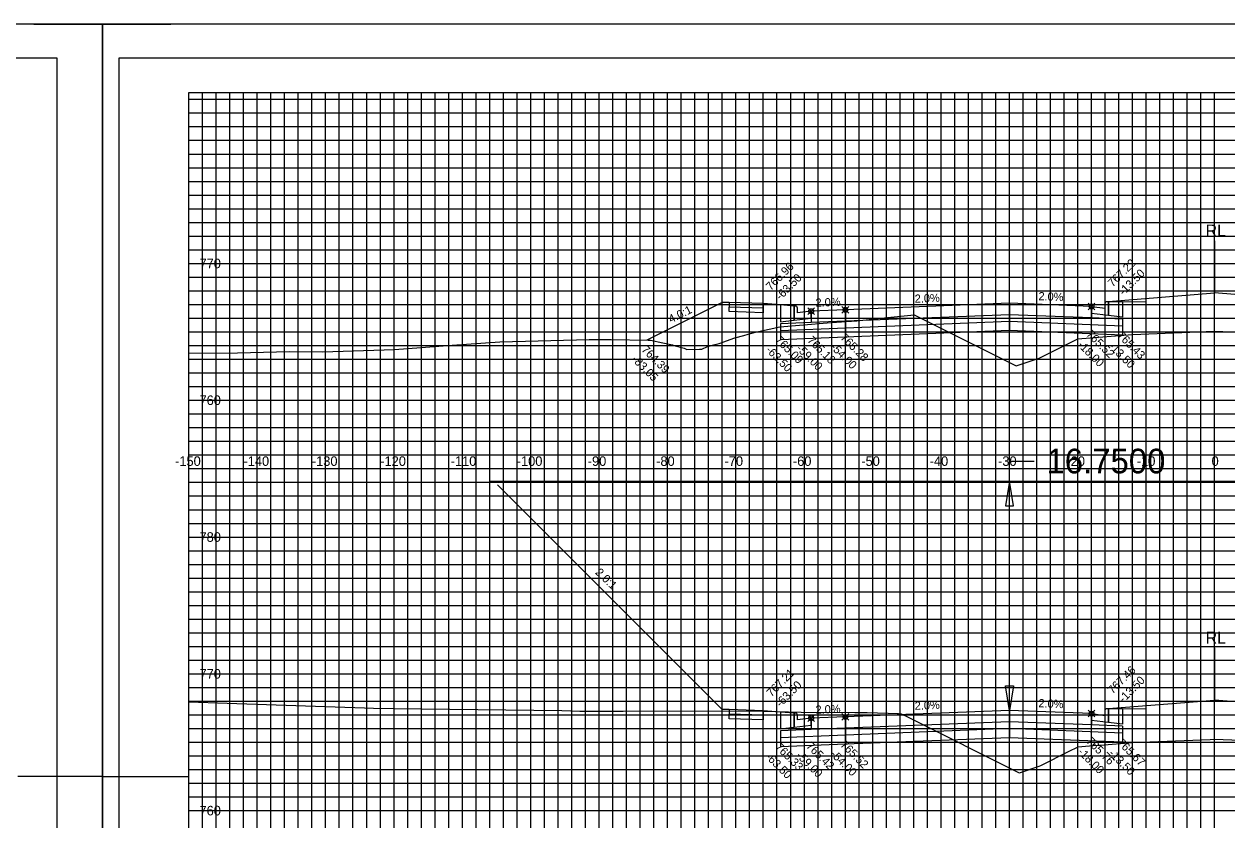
# Model space of a CAD drawing. Extents: x 578243 to 601557, y 174899 to 175559.
# Drawn here: x 600865.7 to 601041.6, y 175002.4 to 175118.8 of the extents above; entities that cross this region are included whole.
import ezdxf

# ---------------------------------------------------------------- set-up
doc = ezdxf.new("R2010")
doc.units = 0
for name, color, linetype in [('E_PROF_Grid', 7, 'Continuous'), ('E_PROF_GridMin', 7, 'Continuous'), ('P_CRDR_Label', 7, 'Continuous'), ('P_CRDR_Link', 7, 'Continuous'), ('P_E_XS_Ground', 7, 'Continuous'), ('P_RW_SlopeIntercepts', 7, 'Continuous'), ('P_XS_Text', 7, 'Continuous'), ('PLT_Sheet_Border', 7, 'Continuous'), ('PLT_Sheet_Info', 7, 'Continuous')]:
    doc.layers.add(name, color=color, linetype=linetype)

msp = doc.modelspace()

# ---------------------------------------------------------------- linework, layer by layer
at = {"layer": 'E_PROF_Grid'}
for p, q in [((600899.84, 174913.8), (600899.84, 175108.8)), ((600909.84, 174913.8), (600909.84, 175108.8)), ((600919.84, 174913.8), (600919.84, 175108.8)), ((600929.84, 174913.8), (600929.84, 175108.8)), ((600939.84, 174913.8), (600939.84, 175108.8)), ((600949.84, 174913.8), (600949.84, 175108.8)), ((600959.84, 174913.8), (600959.84, 175108.8)), ((600969.84, 174913.8), (600969.84, 175108.8)), ((600979.84, 174913.8), (600979.84, 175108.8)), ((600989.84, 174913.8), (600989.84, 175108.8)), ((600999.84, 174913.8), (600999.84, 175108.8)), ((601009.84, 174913.8), (601009.84, 175108.8)), ((601019.84, 174913.8), (601019.84, 175108.8)), ((601029.84, 174913.8), (601029.84, 175108.8)), ((601039.84, 174913.8), (601039.84, 175108.8)), ((600889.84, 175103.8), (601204.84, 175103.8)), ((600889.84, 175093.8), (601204.84, 175093.8)), ((600889.84, 175083.8), (601204.84, 175083.8)), ((600889.84, 175073.8), (601204.84, 175073.8)), ((600889.84, 175063.8), (601204.84, 175063.8)), ((600889.84, 175053.8), (601204.84, 175053.8)), ((600889.84, 175043.8), (601204.84, 175043.8)), ((600889.84, 175033.8), (601204.84, 175033.8)), ((600889.84, 175023.8), (601204.84, 175023.8)), ((600889.84, 175013.8), (601204.84, 175013.8)), ((600889.84, 175003.8), (601204.84, 175003.8))]:
    msp.add_line(p, q, dxfattribs=at)
at = {"layer": 'E_PROF_GridMin'}
for p, q in [((600891.84, 174913.8), (600891.84, 175108.8)), ((600893.84, 174913.8), (600893.84, 175108.8)), ((600895.84, 174913.8), (600895.84, 175108.8)), ((600897.84, 174913.8), (600897.84, 175108.8)), ((600901.84, 174913.8), (600901.84, 175108.8)), ((600903.84, 174913.8), (600903.84, 175108.8)), ((600905.84, 174913.8), (600905.84, 175108.8)), ((600907.84, 174913.8), (600907.84, 175108.8)), ((600911.84, 174913.8), (600911.84, 175108.8)), ((600913.84, 174913.8), (600913.84, 175108.8)), ((600915.84, 174913.8), (600915.84, 175108.8)), ((600917.84, 174913.8), (600917.84, 175108.8)), ((600921.84, 174913.8), (600921.84, 175108.8)), ((600923.84, 174913.8), (600923.84, 175108.8)), ((600925.84, 174913.8), (600925.84, 175108.8)), ((600927.84, 174913.8), (600927.84, 175108.8)), ((600931.84, 174913.8), (600931.84, 175108.8)), ((600933.84, 174913.8), (600933.84, 175108.8)), ((600935.84, 174913.8), (600935.84, 175108.8)), ((600937.84, 174913.8), (600937.84, 175108.8)), ((600941.84, 174913.8), (600941.84, 175108.8)), ((600943.84, 174913.8), (600943.84, 175108.8)), ((600945.84, 174913.8), (600945.84, 175108.8)), ((600947.84, 174913.8), (600947.84, 175108.8)), ((600951.84, 174913.8), (600951.84, 175108.8)), ((600953.84, 174913.8), (600953.84, 175108.8)), ((600955.84, 174913.8), (600955.84, 175108.8)), ((600957.84, 174913.8), (600957.84, 175108.8)), ((600961.84, 174913.8), (600961.84, 175108.8)), ((600963.84, 174913.8), (600963.84, 175108.8)), ((600965.84, 174913.8), (600965.84, 175108.8)), ((600967.84, 174913.8), (600967.84, 175108.8)), ((600971.84, 174913.8), (600971.84, 175108.8)), ((600973.84, 174913.8), (600973.84, 175108.8)), ((600975.84, 174913.8), (600975.84, 175108.8)), ((600977.84, 174913.8), (600977.84, 175108.8)), ((600981.84, 174913.8), (600981.84, 175108.8)), ((600983.84, 174913.8), (600983.84, 175108.8)), ((600985.84, 174913.8), (600985.84, 175108.8)), ((600987.84, 174913.8), (600987.84, 175108.8)), ((600991.84, 174913.8), (600991.84, 175108.8)), ((600993.84, 174913.8), (600993.84, 175108.8)), ((600995.84, 174913.8), (600995.84, 175108.8)), ((600997.84, 174913.8), (600997.84, 175108.8)), ((601001.84, 174913.8), (601001.84, 175108.8)), ((601003.84, 174913.8), (601003.84, 175108.8)), ((601005.84, 174913.8), (601005.84, 175108.8)), ((601007.84, 174913.8), (601007.84, 175108.8)), ((601011.84, 174913.8), (601011.84, 175108.8)), ((601013.84, 174913.8), (601013.84, 175108.8)), ((601015.84, 174913.8), (601015.84, 175108.8)), ((601017.84, 174913.8), (601017.84, 175108.8)), ((601021.84, 174913.8), (601021.84, 175108.8)), ((601023.84, 174913.8), (601023.84, 175108.8)), ((601025.84, 174913.8), (601025.84, 175108.8)), ((601027.84, 174913.8), (601027.84, 175108.8)), ((601031.84, 174913.8), (601031.84, 175108.8)), ((601033.84, 174913.8), (601033.84, 175108.8)), ((601035.84, 174913.8), (601035.84, 175108.8)), ((601037.84, 174913.8), (601037.84, 175108.8)), ((600889.84, 175107.8), (601204.84, 175107.8)), ((600889.84, 175105.8), (601204.84, 175105.8)), ((600889.84, 175101.8), (601204.84, 175101.8)), ((600889.84, 175099.8), (601204.84, 175099.8)), ((600889.84, 175097.8), (601204.84, 175097.8)), ((600889.84, 175095.8), (601204.84, 175095.8)), ((600889.84, 175091.8), (601204.84, 175091.8)), ((600889.84, 175089.8), (601204.84, 175089.8)), ((600889.84, 175087.8), (601204.84, 175087.8)), ((600889.84, 175085.8), (601204.84, 175085.8)), ((600889.84, 175081.8), (601204.84, 175081.8)), ((600889.84, 175079.8), (601204.84, 175079.8)), ((600889.84, 175077.8), (601204.84, 175077.8)), ((600889.84, 175075.8), (601204.84, 175075.8)), ((600889.84, 175071.8), (601204.84, 175071.8)), ((600889.84, 175069.8), (601204.84, 175069.8)), ((600889.84, 175067.8), (601204.84, 175067.8)), ((600889.84, 175065.8), (601204.84, 175065.8)), ((600889.84, 175061.8), (601204.84, 175061.8)), ((600889.84, 175059.8), (601204.84, 175059.8)), ((600889.84, 175057.8), (601204.84, 175057.8)), ((600889.84, 175055.8), (601204.84, 175055.8)), ((600889.84, 175051.8), (601204.84, 175051.8)), ((600889.84, 175049.8), (601204.84, 175049.8)), ((600889.84, 175047.8), (601204.84, 175047.8)), ((600889.84, 175045.8), (601204.84, 175045.8)), ((600889.84, 175041.8), (601204.84, 175041.8)), ((600889.84, 175039.8), (601204.84, 175039.8)), ((600889.84, 175037.8), (601204.84, 175037.8)), ((600889.84, 175035.8), (601204.84, 175035.8)), ((600889.84, 175031.8), (601204.84, 175031.8)), ((600889.84, 175029.8), (601204.84, 175029.8)), ((600889.84, 175027.8), (601204.84, 175027.8)), ((600889.84, 175025.8), (601204.84, 175025.8)), ((600889.84, 175021.8), (601204.84, 175021.8)), ((600889.84, 175019.8), (601204.84, 175019.8)), ((600889.84, 175017.8), (601204.84, 175017.8)), ((600889.84, 175015.8), (601204.84, 175015.8)), ((600889.84, 175011.8), (601204.84, 175011.8)), ((600889.84, 175009.8), (601204.84, 175009.8)), ((600889.84, 175007.8), (601204.84, 175007.8)), ((600889.84, 175005.8), (601204.84, 175005.8))]:
    msp.add_line(p, q, dxfattribs=at)
at = {"layer": 'P_CRDR_Label'}
for points in [[(601039.84, 175087.11), (601039.84, 175079.49)], [(600980.34, 175076.32), (600981.33, 175077.31)], [(600980.34, 175077.31), (600981.33, 175076.32)], [(600985.34, 175076.52), (600986.33, 175077.51)], [(600985.34, 175077.51), (600986.33, 175076.52)], [(601021.34, 175077), (601022.33, 175077.99)], [(601021.34, 175077.99), (601022.33, 175077)], [(601039.84, 175027.6), (601039.84, 175019.97)], [(600980.34, 175016.81), (600981.33, 175017.8)], [(600980.34, 175017.8), (600981.33, 175016.81)], [(600985.34, 175017.01), (600986.33, 175018)], [(600985.34, 175018), (600986.33, 175017.01)], [(601021.34, 175017.49), (601022.33, 175018.48)], [(601021.34, 175018.48), (601022.33, 175017.49)]]:
    msp.add_lwpolyline(points, dxfattribs=at)
for centre in [(600980.84, 175076.82), (600985.84, 175077.02), (601021.84, 175077.5), (600980.84, 175017.3), (600985.84, 175017.5), (601021.84, 175017.98)]:
    msp.add_circle(centre, 0.35, dxfattribs=at)
at = {"layer": 'P_CRDR_Link'}
msp.add_line((600934.99, 175051.44), (600967.84, 175018.59), dxfattribs=at)
for points in [[(601024.34, 175078.25), (601039.84, 175079.49)], [(601024.34, 175078.25), (601039.84, 175079.49)], [(601055.34, 175078.25), (601039.84, 175079.49)], [(601055.34, 175078.25), (601039.84, 175079.49)], [(600967.84, 175078.11), (600956.79, 175072.58)], [(600967.84, 175078.11), (600956.79, 175072.58)], [(600968.84, 175078.08), (600967.84, 175078.11)], [(600968.84, 175078.08), (600967.84, 175078.11)], [(600973.84, 175077.93), (600968.84, 175078.08)], [(600973.84, 175077.93), (600968.84, 175078.08)], [(600968.84, 175078.08), (600968.84, 175077.41)], [(600973.83, 175077.26), (600968.84, 175077.41)], [(600968.85, 175076.75), (600968.84, 175077.41)], [(600973.84, 175077.93), (600973.83, 175077.26)], [(600973.83, 175077.26), (600973.83, 175076.6)], [(600976.34, 175077.73), (600973.84, 175077.93)], [(600976.34, 175077.73), (600973.84, 175077.93)], [(600978.34, 175077.57), (600976.34, 175077.73)], [(600976.34, 175077.73), (600976.34, 175075.25)], [(600976.34, 175077.73), (600976.34, 175075.25)], [(600976.34, 175077.73), (600976.34, 175075.25)], [(600978.66, 175077.57), (600978.34, 175077.57)], [(600978.66, 175077.57), (600978.34, 175077.57)], [(600978.34, 175077.57), (600978.34, 175075.5)], [(600978.34, 175075.5), (600978.34, 175077.57)], [(600978.74, 175077.52), (600978.66, 175077.57)], [(600978.74, 175077.52), (600978.66, 175077.57)], [(600978.8, 175077.41), (600978.74, 175077.52)], [(600978.8, 175077.41), (600978.74, 175077.52)], [(600978.83, 175077.25), (600978.8, 175077.41)], [(600978.83, 175077.25), (600978.8, 175077.41)], [(600978.84, 175076.57), (600978.83, 175077.25)], [(600978.84, 175076.57), (600978.83, 175077.25)], [(600985.84, 175077.02), (600980.84, 175076.82)], [(601009.84, 175077.98), (600985.84, 175077.02)], [(600985.84, 175077.02), (600985.84, 175075.35)], [(600985.84, 175077.02), (600985.84, 175075.35)], [(601021.84, 175077.5), (601009.84, 175077.98)], [(601009.84, 175077.98), (601009.84, 175076.31)], [(601009.84, 175077.98), (601009.84, 175076.31)], [(601021.84, 175077.5), (601023.84, 175077.25)], [(601021.84, 175077.5), (601023.84, 175077.25)], [(601021.84, 175076.5), (601021.84, 175077.5)], [(601021.84, 175077.5), (601021.84, 175075.83)], [(601023.84, 175077.25), (601023.85, 175077.93)], [(601023.84, 175077.25), (601023.85, 175077.93)], [(601023.85, 175077.93), (601023.88, 175078.09)], [(601023.85, 175077.93), (601023.88, 175078.09)], [(601023.88, 175078.09), (601023.94, 175078.2)], [(601023.88, 175078.09), (601023.94, 175078.2)], [(601023.94, 175078.2), (601024.02, 175078.25)], [(601023.94, 175078.2), (601024.02, 175078.25)], [(601024.02, 175078.25), (601024.34, 175078.25)], [(601024.02, 175078.25), (601024.34, 175078.25)], [(601024.34, 175078.25), (601024.34, 175076.18)], [(601024.34, 175078.25), (601026.34, 175078.23)], [(601024.34, 175076.18), (601024.34, 175078.25)], [(601026.34, 175078.23), (601026.34, 175075.93)], [(601026.34, 175078.23), (601026.34, 175075.93)], [(601026.34, 175078.23), (601026.34, 175075.93)], [(601026.34, 175078.23), (601029.84, 175078.2)], [(601026.34, 175078.23), (601029.84, 175078.2)], [(600973.83, 175076.6), (600968.85, 175076.75)], [(600976.34, 175075.25), (600978.34, 175075.5)], [(600980.84, 175075.15), (600976.34, 175074.97)], [(600978.34, 175075.5), (600980.84, 175075.82)], [(600978.34, 175075.5), (600980.84, 175075.82)], [(600980.84, 175076.82), (600978.84, 175076.57)], [(600980.84, 175076.82), (600978.84, 175076.57)], [(600980.84, 175076.82), (600980.84, 175075.15)], [(600980.84, 175075.82), (600980.84, 175076.82)], [(600985.84, 175075.35), (600980.84, 175075.15)], [(601009.84, 175076.31), (600985.84, 175075.35)], [(600985.84, 175075.35), (600985.84, 175074.35)], [(600985.84, 175075.35), (600985.84, 175074.35)], [(601009.84, 175075.31), (600985.84, 175074.35)], [(601021.84, 175075.83), (601009.84, 175076.31)], [(601009.84, 175076.31), (601009.84, 175075.31)], [(601009.84, 175076.31), (601009.84, 175075.31)], [(601026.34, 175074.65), (601009.84, 175075.31)], [(601009.84, 175075.31), (601009.84, 175073.98)], [(601009.84, 175075.31), (601009.84, 175073.98)], [(601024.34, 175076.18), (601021.84, 175076.5)], [(601024.34, 175076.18), (601021.84, 175076.5)], [(601026.34, 175075.65), (601021.84, 175075.83)], [(601026.34, 175075.93), (601024.34, 175076.18)], [(601026.34, 175075.65), (601026.34, 175074.65)], [(600976.34, 175074.97), (600976.34, 175073.97)], [(600985.84, 175074.35), (600976.34, 175073.97)], [(600976.34, 175073.97), (600976.34, 175072.64)], [(600985.84, 175074.35), (600985.84, 175073.02)], [(600985.84, 175074.35), (600985.84, 175073.02)], [(601009.84, 175073.98), (600985.84, 175073.02)], [(601026.34, 175073.32), (601009.84, 175073.98)], [(601026.34, 175074.65), (601026.34, 175073.32)], [(600985.84, 175073.02), (600976.34, 175072.64)], [(601024.34, 175018.73), (601039.84, 175019.97)], [(601024.34, 175018.73), (601039.84, 175019.97)], [(601055.34, 175018.73), (601039.84, 175019.97)], [(601055.34, 175018.73), (601039.84, 175019.97)], [(600968.84, 175018.56), (600967.84, 175018.59)], [(600968.84, 175018.56), (600967.84, 175018.59)], [(600973.84, 175018.41), (600968.84, 175018.56)], [(600973.84, 175018.41), (600968.84, 175018.56)], [(600968.84, 175018.56), (600968.84, 175017.9)], [(600973.83, 175017.75), (600968.84, 175017.9)], [(600968.85, 175017.23), (600968.84, 175017.9)], [(600973.83, 175017.08), (600968.85, 175017.23)], [(600973.84, 175018.41), (600973.83, 175017.75)], [(600973.83, 175017.75), (600973.83, 175017.08)], [(600976.34, 175018.21), (600973.84, 175018.41)], [(600976.34, 175018.21), (600973.84, 175018.41)], [(600978.34, 175018.05), (600976.34, 175018.21)], [(600976.34, 175018.21), (600976.34, 175015.74)], [(600976.34, 175018.21), (600976.34, 175015.74)], [(600976.34, 175018.21), (600976.34, 175015.74)], [(600978.66, 175018.05), (600978.34, 175018.05)], [(600978.66, 175018.05), (600978.34, 175018.05)], [(600978.34, 175018.05), (600978.34, 175015.99)], [(600978.34, 175015.99), (600978.34, 175018.05)], [(600978.74, 175018.01), (600978.66, 175018.05)], [(600978.74, 175018.01), (600978.66, 175018.05)], [(600978.8, 175017.89), (600978.74, 175018.01)], [(600978.8, 175017.89), (600978.74, 175018.01)], [(600978.83, 175017.73), (600978.8, 175017.89)], [(600978.83, 175017.73), (600978.8, 175017.89)], [(600978.84, 175017.05), (600978.83, 175017.73)], [(600978.84, 175017.05), (600978.83, 175017.73)], [(600980.84, 175017.3), (600978.84, 175017.05)], [(600980.84, 175017.3), (600978.84, 175017.05)], [(600985.84, 175017.5), (600980.84, 175017.3)], [(600980.84, 175017.3), (600980.84, 175015.64)], [(600980.84, 175016.3), (600980.84, 175017.3)], [(601009.84, 175018.46), (600985.84, 175017.5)], [(600985.84, 175017.5), (600985.84, 175015.84)], [(600985.84, 175017.5), (600985.84, 175015.84)], [(601021.84, 175017.98), (601009.84, 175018.46)], [(601009.84, 175018.46), (601009.84, 175016.8)], [(601009.84, 175018.46), (601009.84, 175016.8)], [(601021.84, 175017.98), (601023.84, 175017.73)], [(601021.84, 175017.98), (601023.84, 175017.73)], [(601021.84, 175016.98), (601021.84, 175017.98)], [(601021.84, 175017.98), (601021.84, 175016.32)], [(601023.84, 175017.73), (601023.85, 175018.41)], [(601023.84, 175017.73), (601023.85, 175018.41)], [(601023.85, 175018.41), (601023.88, 175018.57)], [(601023.85, 175018.41), (601023.88, 175018.57)], [(601023.88, 175018.57), (601023.94, 175018.69)], [(601023.88, 175018.57), (601023.94, 175018.69)], [(601023.94, 175018.69), (601024.02, 175018.73)], [(601023.94, 175018.69), (601024.02, 175018.73)], [(601024.02, 175018.73), (601024.34, 175018.73)], [(601024.02, 175018.73), (601024.34, 175018.73)], [(601024.34, 175018.73), (601024.34, 175016.67)], [(601024.34, 175018.73), (601026.34, 175018.72)], [(601024.34, 175016.67), (601024.34, 175018.73)], [(601026.34, 175018.72), (601026.34, 175016.42)], [(601026.34, 175018.72), (601026.34, 175016.42)], [(601026.34, 175018.72), (601026.34, 175016.42)], [(601026.34, 175018.72), (601029.84, 175018.69)], [(601026.34, 175018.72), (601029.84, 175018.69)], [(600976.34, 175015.74), (600978.34, 175015.99)], [(600980.84, 175015.64), (600976.34, 175015.46)], [(600976.34, 175015.46), (600976.34, 175014.46)], [(600978.34, 175015.99), (600980.84, 175016.3)], [(600978.34, 175015.99), (600980.84, 175016.3)], [(600985.84, 175015.84), (600980.84, 175015.64)], [(601009.84, 175016.8), (600985.84, 175015.84)], [(600985.84, 175015.84), (600985.84, 175014.84)], [(600985.84, 175015.84), (600985.84, 175014.84)], [(601009.84, 175015.8), (600985.84, 175014.84)], [(601021.84, 175016.32), (601009.84, 175016.8)], [(601009.84, 175016.8), (601009.84, 175015.8)], [(601009.84, 175016.8), (601009.84, 175015.8)], [(601026.34, 175015.14), (601009.84, 175015.8)], [(601009.84, 175015.8), (601009.84, 175014.46)], [(601009.84, 175015.8), (601009.84, 175014.46)], [(601024.34, 175016.67), (601021.84, 175016.98)], [(601024.34, 175016.67), (601021.84, 175016.98)], [(601026.34, 175016.14), (601021.84, 175016.32)], [(601026.34, 175016.42), (601024.34, 175016.67)], [(601026.34, 175016.14), (601026.34, 175015.14)], [(600985.84, 175014.84), (600976.34, 175014.46)], [(600976.34, 175014.46), (600976.34, 175013.12)], [(600985.84, 175014.84), (600985.84, 175013.5)], [(600985.84, 175014.84), (600985.84, 175013.5)], [(601009.84, 175014.46), (600985.84, 175013.5)], [(601026.34, 175013.8), (601009.84, 175014.46)], [(601026.34, 175015.14), (601026.34, 175013.8)], [(600985.84, 175013.5), (600976.34, 175013.12)]]:
    msp.add_lwpolyline(points, dxfattribs=at)
at = {"layer": 'P_E_XS_Ground'}
for points in [[(600889.84, 175070.7), (600896.96, 175070.72), (600904.56, 175070.92), (600909.37, 175070.87), (600919.9, 175071.24), (600928.35, 175071.83), (600935.33, 175072.33), (600948.38, 175072.68), (600949.06, 175072.69), (600949.45, 175072.66), (600951.58, 175072.67), (600957, 175072.58), (600957.36, 175072.59), (600959.13, 175072.2), (600960.56, 175071.88), (600960.77, 175071.78), (600962.29, 175071.41), (600962.66, 175071.23), (600964.5, 175071.26), (600964.84, 175071.29), (600965.69, 175071.66), (600966.8, 175071.93), (600967.37, 175072.08), (600969.69, 175072.91), (600970.97, 175073.26), (600971.63, 175073.45), (600972.71, 175073.76), (600974.68, 175074.21), (600976.27, 175074.51), (600983.18, 175075.14), (600985.96, 175075.33), (600987.53, 175075.42), (600991.98, 175075.89), (600995.91, 175076.29), (601010.81, 175068.84), (601014.2, 175069.97), (601018.54, 175072.14), (601019.84, 175072.79), (601022.84, 175073.03), (601027.84, 175073.43), (601039.84, 175073.91), (601056.84, 175073.23)], [(600889.84, 175019.7), (600895.44, 175019.53), (600915.52, 175018.84), (600916.84, 175018.79), (600919.81, 175018.73), (600944.36, 175018.42), (600947.03, 175018.36), (600953.36, 175018.32), (600965.79, 175018.38), (600973.75, 175018.36), (600979.36, 175018.21), (600987.21, 175018.14), (600989.05, 175018.17), (600993.59, 175017.99), (600994.02, 175017.94), (600995.02, 175017.44), (601011.25, 175009.32), (601011.43, 175009.38), (601014.2, 175010.3), (601014.43, 175010.42), (601018.54, 175012.48), (601019.77, 175013.09), (601019.84, 175013.13), (601022.68, 175013.35), (601022.84, 175013.37), (601023.11, 175013.39), (601027.84, 175013.77), (601039.19, 175014.22), (601039.84, 175014.25), (601051.19, 175013.79)]]:
    msp.add_lwpolyline(points, dxfattribs=at)
at = {"layer": 'P_RW_SlopeIntercepts'}
for p, q in [((601009.84, 175054.89), (601013.44, 175054.89)), ((601009.84, 175018.46), (601009.84, 175054.89)), ((600933.84, 175051.96), (601169.84, 175051.96)), ((601009.84, 175051.96), (601009.24, 175048.36)), ((601010.44, 175048.36), (601009.84, 175051.96)), ((601009.24, 175048.36), (601010.44, 175048.36)), ((601009.24, 175022.06), (601010.44, 175022.06)), ((601009.84, 175018.46), (601009.24, 175022.06)), ((601010.44, 175022.06), (601009.84, 175018.46))]:
    msp.add_line(p, q, dxfattribs=at)
at = {"layer": 'PLT_Sheet_Border'}
for points in [[(600537.19, 174898.8), (600877.19, 174898.8), (600877.19, 175118.8), (600537.19, 175118.8)], [(600877.19, 174898.8), (601217.19, 174898.8), (601217.19, 175118.8), (600877.19, 175118.8)], [(600539.59, 174903.8), (600870.59, 174903.8), (600870.59, 175113.8), (600539.59, 175113.8)], [(600879.59, 174903.8), (601210.59, 174903.8), (601210.59, 175113.8), (600879.59, 175113.8)]]:
    msp.add_lwpolyline(points, close=True, dxfattribs=at)
at = {"layer": 'PLT_Sheet_Info'}
for p, q in [((600867.19, 175118.8), (600877.19, 175118.8)), ((600877.19, 175108.8), (600877.19, 175118.8)), ((600877.19, 175108.8), (600877.19, 175118.8)), ((600877.19, 175118.8), (600887.19, 175118.8)), ((600889.84, 175108.8), (601204.84, 175108.8)), ((600889.84, 174908.8), (600889.84, 175108.8)), ((600877.19, 175003.8), (600877.19, 175013.8)), ((600877.19, 175003.8), (600877.19, 175013.8)), ((600877.19, 175008.8), (600864.84, 175008.8)), ((600877.19, 175008.8), (600889.84, 175008.8))]:
    msp.add_line(p, q, dxfattribs=at)

# ---------------------------------------------------------------- texts
at = {"layer": 'P_CRDR_Label'}
for p in [(601038.51, 175087.74), (601038.51, 175028.22)]:
    msp.add_text('RL', height=1.75, dxfattribs=at).set_placement(p)
for s, rotation, p in [('766.96', 45, (600974.93, 175079.77)), ('767.22', 45, (601024.93, 175080.27)), ('-63.50', 45, (600976.35, 175078.36)), ('-13.50', 45, (601026.52, 175079.04)), ('2.0%', 2.2906, (600981.5, 175077.46)), ('2.0%', 2.2906, (600996, 175078.04)), ('2.0%', 357.7094, (601014.05, 175078.43)), ('4.0:1', 26.5651, (600960.34, 175075.05)), ('765.28', 315, (600985.02, 175072.84)), ('765.52', 315, (601020.99, 175073.35)), ('765.43', 315, (601025.49, 175073.17)), ('764.39', 315, (600955.94, 175071.1)), ('764.39', 315, (600955.94, 175071.1)), ('765.09', 315, (600975.49, 175072.49)), ('-59.00', 315, (600978.58, 175071.26)), ('765.18', 315, (600980.2, 175072.46)), ('-54.00', 315, (600983.58, 175071.46)), ('-18.00', 315, (601019.73, 175071.79)), ('-13.50', 315, (601024.25, 175071.58)), ('-83.05', 315, (600954.53, 175069.68)), ('-83.05', 315, (600954.53, 175069.68)), ('-63.50', 315, (600974.11, 175071.05)), ('2.0:1', 315.8532, (600949.19, 175038.52)), ('767.21', 45, (600975.03, 175020.36)), ('767.46', 45, (601024.93, 175020.76)), ('-63.50', 45, (600976.34, 175018.84)), ('-13.50', 45, (601026.52, 175019.52)), ('2.0%', 2.2906, (600981.5, 175017.95)), ('2.0%', 2.2906, (600996, 175018.53)), ('2.0%', 357.7094, (601014.05, 175018.92)), ('765.33', 315, (600975.49, 175012.98)), ('765.42', 315, (600980.03, 175013.13)), ('765.52', 315, (600985.02, 175013.33)), ('765.76', 315, (601020.99, 175013.84)), ('765.67', 315, (601025.49, 175013.66)), ('-63.50', 315, (600974.08, 175011.57)), ('-59.00', 315, (600978.58, 175011.75)), ('-54.00', 315, (600983.58, 175011.95)), ('-18.00', 315, (601019.73, 175012.28)), ('-13.50', 315, (601024.25, 175012.07))]:
    msp.add_text(s, height=1.2, rotation=rotation, dxfattribs=at).set_placement(p)
at = {"layer": 'P_RW_SlopeIntercepts'}
msp.add_text('16.7500', height=3.6, dxfattribs=at).set_placement((601015.24, 175053.11))
at = {"layer": 'P_XS_Text'}
for s, p in [('770', (600891.4, 175083.1)), ('760', (600891.4, 175063.1)), ('-150', (600887.83, 175054.2)), ('-140', (600897.83, 175054.2)), ('-130', (600907.83, 175054.2)), ('-120', (600917.83, 175054.2)), ('-110', (600928.13, 175054.2)), ('-100', (600937.79, 175054.2)), ('-90', (600948.17, 175054.2)), ('-80', (600958.17, 175054.2)), ('-70', (600968.17, 175054.2)), ('-60', (600978.17, 175054.2)), ('-50', (600988.17, 175054.2)), ('-40', (600998.17, 175054.2)), ('-30', (601008.17, 175054.2)), ('-20', (601018.17, 175054.2)), ('-10', (601028.47, 175054.2)), ('0', (601039.39, 175054.2)), ('0', (601039.39, 175054.2)), ('780', (600891.4, 175043.1)), ('770', (600891.4, 175023.1)), ('760', (600891.4, 175003.1))]:
    msp.add_text(s, height=1.4, rotation=360, dxfattribs=at).set_placement(p)

doc.saveas('drawing.dxf')
